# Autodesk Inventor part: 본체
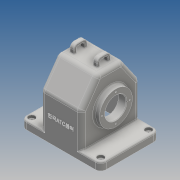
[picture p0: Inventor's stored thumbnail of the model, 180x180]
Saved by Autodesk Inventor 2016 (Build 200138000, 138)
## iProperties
Created: 2016-12
Part Number: 본체
Material: Generic
Document SubType Name: Modeling
Designer: Administrator
Density: 1 g/cm^3
Appearance: Default
Author: Administrator
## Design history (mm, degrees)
sketch "스케치1"
  geometry: L1 (-75, -55)-(75, -55); L2 (75, -55)-(75, 55); L3 (75, 55)-(-75, 55); L4 (-75, 55)-(-75, -55); L5 (-75, -55)-(75, 55); L6 (75, -55)-(-75, 55); 1 further point
  constraints: 12 end point, 2 midpoint, 2 parallel, 1 horizontal, 1 perpendicular
  dimensions: "d0" = 150 distance of L2.end L3.end; "d1" = 110 distance of L1.end L2.end
extrude "돌출1" new body sketch "스케치1" distance "d2" = 15; taper "d3" = 0 deg
sketch "스케치2"
  geometry: L1 (55, 15)-(-55, 15) reference; L2 (-55, 15)-(-55, 80); L3 (-55, 80)-(-23.491, 125); L4 (-23.491, 125)-(23.491, 125); L5 (23.491, 125)-(55, 80); L6 (55, 80)-(55, 15); L7 (0, 0)-(0, 125); L8 (55, 0)-(-55, 0) reference; 1 further point
  constraints: 12 end point, 3 point on line, 2 midpoint, 2 perpendicular, 2 vertical, 1 coincident, 1 vertical alignment, 2 other
  dimensions: "d4" = 125 distance between parallel lines of L4 L8; "d5" = 80 distance from line of L5.end L8; "d6" = 35 deg angle of L2 L3
extrude "돌출2" join sketch "스케치2" stored distance "d7" = 77; taper "d8" = 0 deg
fillet "모깎기1" dims "d9" = 10
node "작업 평면2"
sketch "스케치4"
  geometry: L1 (-18.285, 125)-(18.285, 125) reference; L2 (-12.5, 125)-(-12.5, 140); L3 (-12.5, 140)-(12.5, 140); L4 (12.5, 140)-(12.5, 125); L5 (-7.5, 125)-(-7.5, 135); L6 (-7.5, 135)-(7.5, 135); L7 (7.5, 135)-(7.5, 125); L8 (55, 0)-(-55, 0) reference; 4 further points
  constraints: 12 end point, 4 perpendicular, 4 point on line, 3 midpoint, 2 vertical, 2 vertical alignment
  dimensions: "d18" = 25 distance of L2.end L3.end; "d19" = 15 distance of L5.end L6.end; "d20" = 5 distance between parallel lines of L6 L3; "d21" = 140 distance between parallel lines of L3 L8
extrude "돌출4" join sketch "스케치4" distance "d22" = 8; taper "d23" = 0 deg
fillet "모깎기2" dims "d24" = 8
fillet "모깎기3" dims "d25" = 3
sketch "스케치5"
  geometry: L1 (55, 76.847)-(55, 0) reference; L2 (55, 0)-(-55, 0) reference; L3 (-55, 0)-(-55, 76.847) reference; L4 (-53.192, 82.583)-(-26.477, 120.736) reference; L5 (-18.285, 125)-(18.285, 125) reference; L6 (26.477, 120.736)-(53.192, 82.583) reference; L7 (18.285, 120)-(-18.285, 120); L8 (-22.381, 117.868)-(-49.096, 79.715); L9 (-50, 76.847)-(-50, 0); L10 (50, 0)-(50, 76.847); L11 (49.096, 79.715)-(22.381, 117.868); L12 (55, 0)-(-55, 0) reference; L13 (-50, 0)-(50, 0); A1 r 10 centre (-45, 76.847) between (-53.192, 82.583) and (-55, 76.847) reference; A2 r 10 centre (-18.285, 115) between (-18.285, 125) and (-26.477, 120.736) reference; A3 r 10 centre (18.285, 115) between (26.477, 120.736) and (18.285, 125) reference; A4 r 10 centre (45, 76.847) between (55, 76.847) and (53.192, 82.583) reference; A5 r 5 centre (-18.285, 115) between (-18.285, 120) and (-22.381, 117.868); A6 r 5 centre (-45, 76.847) between (-49.096, 79.715) and (-50, 76.847); A7 r 5 centre (45, 76.847) between (50, 76.847) and (49.096, 79.715); A8 r 5 centre (18.285, 115) between (22.381, 117.868) and (18.285, 120); 1 further point
  constraints: 12 end point, 8 point on circle, 4 centre point, 2 point on line, 1 horizontal, 5 other
  dimensions: "d26" = 5 distance between parallel lines of L5 L7; "d27" = 5 distance between parallel lines of L11 L6; "d28" = 5 distance between parallel lines of L9 L3; "d29" = 5 distance between parallel lines of L1 L10
extrude "돌출5" cut sketch "스케치5" stored distance "d30" = 67; taper "d31" = 0 deg
fillet "모깎기4" dims "d32" = 3
sketch "스케치6"
  geometry: L1 (0, 55)-(0, -55) reference; C1 r 37.5 at (65, 0); 2 further points
  constraints: 1 centre point, 1 horizontal alignment, 1 midpoint
  dimensions: "d33" = 75 diameter of C1; "d34" = 65 distance from line of C1.centre L1
extrude "돌출6" join sketch "스케치6" distance "d35" = 5; taper "d36" = 0 deg
sketch "스케치7"
  geometry: L1 (0, -55)-(0, 55) reference; C1 r 31 at (-65, 0); 2 further points
  constraints: 1 centre point, 1 horizontal alignment, 1 midpoint
  dimensions: "d37" = 62 diameter of C1; "d38" = 65 distance from line of C1.centre L1
extrude "돌출7" join sketch "스케치7" distance "d39" = 10; taper "d40" = 0 deg
sketch "스케치8"
  geometry: L1 (43.5, 27.5)-(43.5, 102.5) reference; L2 (-48.5, 96)-(-48.5, 34) reference; L3 (43.5, 65)-(-48.5, 65); L4 (33.5, 116.147)-(33.5, 77.994) reference; L5 (33.5, 106)-(19.5, 92); L6 (19.5, 92)-(19.5, 65); L7 (33.5, 106)-(33.5, 65); 1 further point
  constraints: 8 end point, 3 point on line, 2 midpoint, 2 perpendicular
  dimensions: "d41" = 45 deg angle of L5 L6; "d42" = 54 diameter of L5.end L3; "d43" = 24 distance between parallel lines of L1 L6
revolve "회전1" sketch "스케치8" stored, may be unused: angle "d44" = 90 deg
hole "구멍1" diameter "d47" = 40; stored, may be unused: countersink angle "d51" = 90 deg, drill point angle "d53" = 0 deg; dims "d45" = 10, "d46" = 10, "d48" = 6, "d49" = 4, "d50" = 2, "d52" = 8
sketch "스케치9"
  geometry: C1 r 20 at (0, 0) reference; 5 further points
  constraints: 1 horizontal alignment, 5 other
  dimensions: "d54" = 26 distance of point (-26, 0) C1.centre; "d57" = 360 deg dimension on C1.centre point (-26, 0) (derived)
hole "구멍2" sketch "스케치9" at (-26, 0), (0, -26), (26, 0), (0, 26) diameter "d59" = 2.459; stored, may be unused: countersink angle "d63" = 90 deg, drill point angle "d65" = 118 deg; dims "d60" = 6, "d61" = 4, "d62" = 2, "d64" = 8
sketch "스케치10"
  geometry: C1 r 20 at (0, 0) reference; C2 r 37.5 at (0, 0) reference; 5 further points
  constraints: 1 horizontal alignment, 5 other
  dimensions: "d66" = 29 distance of point (29, 0) C1.centre; "d69" = 360 deg dimension on C1.centre point (29, 0) (derived)
hole "구멍3" sketch "스케치10" at (29, 0), (0, 29), (-29, 0), (0, -29) diameter "d71" = 2.459; stored, may be unused: countersink angle "d75" = 90 deg, drill point angle "d77" = 118 deg; dims "d72" = 6, "d73" = 4, "d74" = 2, "d76" = 8
fillet "모깎기5" dims "d78" = 10
sketch "스케치11"
  geometry: A1 r 10 centre (65, 45) between (75, 45) and (65, 55) reference; A2 r 10 centre (65, -45) between (65, -55) and (75, -45) reference; A3 r 10 centre (-65, 45) between (-65, 55) and (-75, 45) reference; A4 r 10 centre (-65, -45) between (-75, -45) and (-65, -55) reference; 5 further points
  constraints: 4 coincident
hole "구멍4" sketch "스케치11" at (-65, 45), (-65, -45), (65, -45), (65, 45) diameter "d79" = 5; stored, may be unused: countersink angle "d83" = 90 deg, drill point angle "d85" = 0 deg; dims "d80" = 6, "d81" = 12, "d82" = 5, "d84" = 8
fillet "모깎기6" dims "d86" = 3
sketch "스케치12" dims "d9" = 10
  geometry: L1 (-34.5, -76.847)-(95.5, -76.847) reference; 3 further points
  constraints: 1 midpoint, 1 vertical alignment, 1 other
  dimensions: "d87" = 45 distance from line of point (30.5, -31.847) L1
feature "엠보싱1" sketch "스케치12" dims "d0" = 150, "d1" = 110, "d9" = 10, "d88" = 0.5, "d89" = 0
fillet "모깎기7" dims "d90" = 1
chamfer "모따기1" distance "d91" = 1; stored, may be unused: second distance "d92" = 2, angle "d93" = 45 deg
node "솔리드1"
mirror "대칭1"
node "절단 모서리 투영1"
other parameters: "d17" = 18
